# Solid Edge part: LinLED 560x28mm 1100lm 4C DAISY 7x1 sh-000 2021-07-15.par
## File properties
Author: radoslaw.kuczynski
Template: iso metric part.par
Last saved by: radoslaw.kuczynski
Revision: 1
Application: Solid Edge
Gęstość: 0,000 kg/m^3
Dokładność: 0,990
Username: radoslaw.kuczynski
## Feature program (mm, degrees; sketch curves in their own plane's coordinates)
body "unnamed Body 1"
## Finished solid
Body 1: solid body, 1908 faces, 4898 edges, 3120 vertices, 2 separate solids.
  Faces by surface: plane 1309, cylinder 277, spline 192, cone 60, sphere 32, torus 20, spun 16, swept 2
  Edges by curve: line 3628, curve on surface 652, circle 378, ellipse 132, spline 100, intersection 8
Bounding box of the edges (mm; curved faces can reach further): 559.000 x 4.500 x 28.000, from (-279.5, -3.5, -14) to (279.5, 1, 14).
Cylindrical faces by radius (mm): R0.2 x92, R0.2169 x12, R0.25 x24, R0.3373 x12, R0.4 x16, R0.4006 x4, R0.4008 x4, R0.525 x4, R0.6 x40, R0.75 x1, R1 x28, R1.1 x8, R1.2 x20, R1.7 x12
Conical faces (half-angle, radius in mm at the cone's reference point): 0.5 deg R0.5056 x8, 0.5 deg R1.0082 x8, 1 deg R0.5511 x4, 10 deg R0.2132 x8, 10 deg R0.4132 x8, 18.8604 deg R1.0669 x8, 27.363 deg R0.6214 x4, 45 deg R0.575 x4, 45 deg R0.625 x8
Toroidal faces (ring radius, tube radius in mm): R0.8 r0.2 x8, R0.8522 r0.3 x4, R0.9002 r0.2 x4, R0.9018 r0.2 x4
Spherical faces by radius (mm): R0.2 x24, R0.6 x8
Planar faces by outward normal: +x 115, +y 19, +z 122, -x 115, -y 220, -z 124, oblique 594
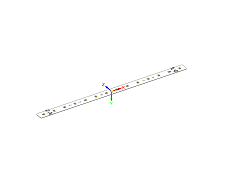
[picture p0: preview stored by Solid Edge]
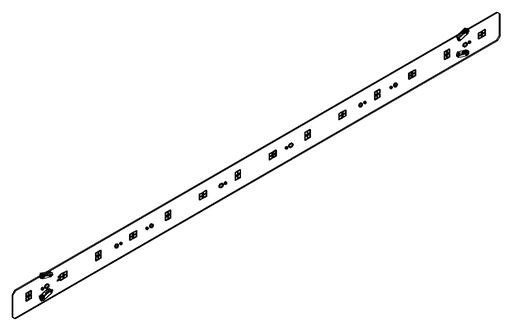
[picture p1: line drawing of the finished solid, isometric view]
